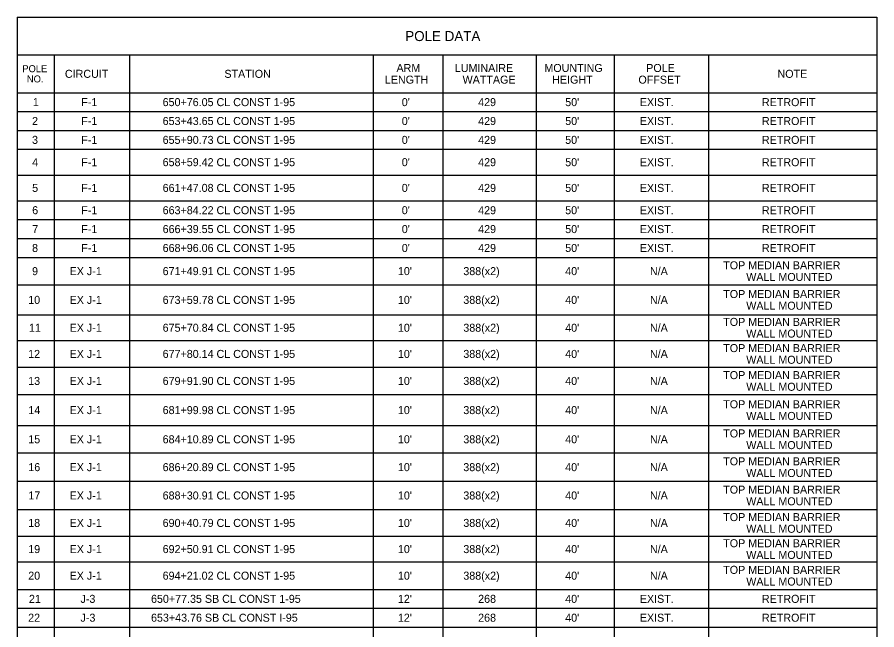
# Model space of a CAD drawing. Extents: x -838.2 to -802.1, y -2200.5 to -2187.7.
# Drawn here: x -838.21 to -830.69, y -2195.1 to -2189.75 of the extents above; entities that cross this region are included whole.
import ezdxf

# ---------------------------------------------------------------- set-up
doc = ezdxf.new("R2010")
doc.units = 0
for name, color, linetype in [('SumBoxBorder_dp', 7, 'Continuous'), ('SumBoxLines_dp', 7, 'Continuous'), ('SumBoxLinesMin_dp', 7, 'Continuous'), ('TextLabel', 7, 'Continuous')]:
    doc.layers.add(name, color=color, linetype=linetype)

msp = doc.modelspace()

# ---------------------------------------------------------------- linework, layer by layer
at = {"layer": 'SumBoxBorder_dp'}
for p, q in [((-838.2083, -2189.7484), (-830.6933, -2189.7484)), ((-838.2083, -2189.7484), (-838.2083, -2199.1009)), ((-830.6933, -2189.7484), (-830.6933, -2199.1009)), ((-830.6933, -2189.7484), (-830.6933, -2199.1009)), ((-838.2083, -2190.0784), (-830.6933, -2190.0784)), ((-838.2083, -2190.0784), (-830.6933, -2190.0784))]:
    msp.add_line(p, q, dxfattribs=at)
at = {"layer": 'SumBoxLines_dp'}
for p, q in [((-837.8858, -2190.0784), (-837.8858, -2199.1009)), ((-837.8858, -2190.0784), (-837.8858, -2199.1009)), ((-837.2258, -2190.0784), (-837.2258, -2199.1009)), ((-837.2258, -2190.0784), (-837.2258, -2199.1009)), ((-835.0958, -2190.0784), (-835.0958, -2197.0609)), ((-835.0958, -2190.0784), (-835.0958, -2199.1009)), ((-834.4883, -2190.0784), (-834.4883, -2199.1009)), ((-834.4883, -2190.0784), (-834.4883, -2199.1009)), ((-833.6708, -2190.0784), (-833.6708, -2199.1009)), ((-833.6708, -2190.0784), (-833.6708, -2199.1009)), ((-832.9883, -2190.0784), (-832.9883, -2199.1009)), ((-832.9883, -2190.0784), (-832.9883, -2199.1009)), ((-832.1633, -2190.0784), (-832.1633, -2199.1009)), ((-832.1633, -2190.0784), (-832.1633, -2199.1009)), ((-838.2083, -2190.4084), (-830.6933, -2190.4084))]:
    msp.add_line(p, q, dxfattribs=at)
at = {"layer": 'SumBoxLinesMin_dp'}
for p, q in [((-838.2083, -2190.4084), (-830.6933, -2190.4084)), ((-838.2083, -2190.5734), (-830.6933, -2190.5734)), ((-838.2083, -2190.5734), (-830.6933, -2190.5734)), ((-838.2083, -2190.7384), (-830.6933, -2190.7384)), ((-838.2083, -2190.7384), (-830.6933, -2190.7384)), ((-838.2083, -2190.9034), (-830.6933, -2190.9034)), ((-838.2083, -2190.9034), (-830.6933, -2190.9034)), ((-838.2083, -2191.1284), (-830.6933, -2191.1284)), ((-838.2083, -2191.1284), (-830.6933, -2191.1284)), ((-838.2083, -2191.3534), (-830.6933, -2191.3534)), ((-838.2083, -2191.3534), (-830.6933, -2191.3534)), ((-838.2083, -2191.5184), (-830.6933, -2191.5184)), ((-838.2083, -2191.5184), (-830.6933, -2191.5184)), ((-838.2083, -2191.6834), (-830.6933, -2191.6834)), ((-838.2083, -2191.6834), (-830.6933, -2191.6834)), ((-838.2083, -2191.8484), (-830.6933, -2191.8484)), ((-838.2083, -2191.8484), (-830.6933, -2191.8484)), ((-838.2083, -2192.0884), (-830.6933, -2192.0884)), ((-838.2083, -2192.0884), (-830.6933, -2192.0884)), ((-838.2083, -2192.3509), (-830.6933, -2192.3509)), ((-838.2083, -2192.3509), (-830.6933, -2192.3509)), ((-838.2083, -2192.5759), (-830.6933, -2192.5759)), ((-838.2083, -2192.5759), (-830.6933, -2192.5759)), ((-838.2083, -2192.8084), (-830.6933, -2192.8084)), ((-838.2083, -2192.8084), (-830.6933, -2192.8084)), ((-838.2083, -2193.0484), (-830.6933, -2193.0484)), ((-838.2083, -2193.0484), (-830.6933, -2193.0484)), ((-838.2083, -2193.3184), (-830.6933, -2193.3184)), ((-838.2083, -2193.3184), (-830.6933, -2193.3184)), ((-838.2083, -2193.5584), (-830.6933, -2193.5584)), ((-838.2083, -2193.5584), (-830.6933, -2193.5584)), ((-838.2083, -2193.8059), (-830.6933, -2193.8059)), ((-838.2083, -2193.8059), (-830.6933, -2193.8059)), ((-838.2083, -2194.0534), (-830.6933, -2194.0534)), ((-838.2083, -2194.0534), (-830.6933, -2194.0534)), ((-838.2083, -2194.2859), (-830.6933, -2194.2859)), ((-838.2083, -2194.2859), (-830.6933, -2194.2859)), ((-838.2083, -2194.5109), (-830.6933, -2194.5109)), ((-838.2083, -2194.5109), (-830.6933, -2194.5109)), ((-838.2083, -2194.7509), (-830.6933, -2194.7509)), ((-838.2083, -2194.7509), (-830.6933, -2194.7509)), ((-838.2083, -2194.9159), (-830.6933, -2194.9159)), ((-838.2083, -2194.9159), (-830.6933, -2194.9159)), ((-838.2083, -2195.0809), (-830.6933, -2195.0809)), ((-838.2083, -2195.0809), (-830.6933, -2195.0809))]:
    msp.add_line(p, q, dxfattribs=at)

# ---------------------------------------------------------------- texts
at = {"layer": 'TextLabel'}
for s, height, p in [('POLE DATA', 0.0875, (-834.8157, -2189.9572)), ('POLE', 0.06125, (-838.1637, -2190.2294)), ('ARM', 0.07, (-834.8926, -2190.2274)), ('LUMINAIRE', 0.07, (-834.3823, -2190.2274)), ('MOUNTING', 0.07, (-833.5993, -2190.2274)), ('POLE', 0.07, (-832.7091, -2190.2274)), ('CIRCUIT', 0.07, (-837.7912, -2190.2784)), ('STATION', 0.07, (-836.3967, -2190.2784)), ('NOTE', 0.07, (-831.5616, -2190.2784)), ('NO.', 0.06125, (-838.1238, -2190.3187)), ('LENGTH', 0.07, (-834.994, -2190.3294)), ('WATTAGE', 0.07, (-834.3145, -2190.3294)), ('HEIGHT', 0.07, (-833.5311, -2190.3294)), ('OFFSET', 0.07, (-832.7773, -2190.3294)), ('1', 0.07, (-838.0718, -2190.5259)), ('F-1', 0.07, (-837.6483, -2190.5259)), ('650+76.05 CL CONST 1-95', 0.07, (-836.9367, -2190.5259)), ("0'", 0.07, (-834.8462, -2190.5259)), ('429', 0.07, (-834.1784, -2190.5259)), ("50'", 0.07, (-833.4175, -2190.5259)), ('EXIST.', 0.07, (-832.7651, -2190.5259)), ('RETROFIT', 0.07, (-831.6976, -2190.5259)), ('2', 0.07, (-838.0785, -2190.6909)), ('F-1', 0.07, (-837.6483, -2190.6909)), ('653+43.65 CL CONST 1-95', 0.07, (-836.9367, -2190.6909)), ("0'", 0.07, (-834.8462, -2190.6909)), ('429', 0.07, (-834.1784, -2190.6909)), ("50'", 0.07, (-833.4175, -2190.6909)), ('EXIST.', 0.07, (-832.7651, -2190.6909)), ('RETROFIT', 0.07, (-831.6976, -2190.6909)), ('3', 0.07, (-838.0785, -2190.8559)), ('F-1', 0.07, (-837.6483, -2190.8559)), ('655+90.73 CL CONST 1-95', 0.07, (-836.9367, -2190.8559)), ("0'", 0.07, (-834.8462, -2190.8559)), ('429', 0.07, (-834.1784, -2190.8559)), ("50'", 0.07, (-833.4175, -2190.8559)), ('EXIST.', 0.07, (-832.7651, -2190.8559)), ('RETROFIT', 0.07, (-831.6976, -2190.8559)), ('4', 0.07, (-838.0771, -2191.0509)), ('F-1', 0.07, (-837.6483, -2191.0509)), ('658+59.42 CL CONST 1-95', 0.07, (-836.9367, -2191.0509)), ("0'", 0.07, (-834.8462, -2191.0509)), ('429', 0.07, (-834.1784, -2191.0509)), ("50'", 0.07, (-833.4175, -2191.0509)), ('EXIST.', 0.07, (-832.7651, -2191.0509)), ('RETROFIT', 0.07, (-831.6976, -2191.0509)), ('5', 0.07, (-838.0776, -2191.2759)), ('F-1', 0.07, (-837.6483, -2191.2759)), ('661+47.08 CL CONST 1-95', 0.07, (-836.9367, -2191.2759)), ("0'", 0.07, (-834.8462, -2191.2759)), ('429', 0.07, (-834.1784, -2191.2759)), ("50'", 0.07, (-833.4175, -2191.2759)), ('EXIST.', 0.07, (-832.7651, -2191.2759)), ('RETROFIT', 0.07, (-831.6976, -2191.2759)), ('6', 0.07, (-838.0771, -2191.4709)), ('F-1', 0.07, (-837.6483, -2191.4709)), ('663+84.22 CL CONST 1-95', 0.07, (-836.9367, -2191.4709)), ("0'", 0.07, (-834.8462, -2191.4709)), ('429', 0.07, (-834.1784, -2191.4709)), ("50'", 0.07, (-833.4175, -2191.4709)), ('EXIST.', 0.07, (-832.7651, -2191.4709)), ('RETROFIT', 0.07, (-831.6976, -2191.4709)), ('7', 0.07, (-838.0765, -2191.6359)), ('F-1', 0.07, (-837.6483, -2191.6359)), ('666+39.55 CL CONST 1-95', 0.07, (-836.9367, -2191.6359)), ("0'", 0.07, (-834.8462, -2191.6359)), ('429', 0.07, (-834.1784, -2191.6359)), ("50'", 0.07, (-833.4175, -2191.6359)), ('EXIST.', 0.07, (-832.7651, -2191.6359)), ('RETROFIT', 0.07, (-831.6976, -2191.6359)), ('8', 0.07, (-838.0783, -2191.8009)), ('F-1', 0.07, (-837.6483, -2191.8009)), ('668+96.06 CL CONST 1-95', 0.07, (-836.9367, -2191.8009)), ("0'", 0.07, (-834.8462, -2191.8009)), ('429', 0.07, (-834.1784, -2191.8009)), ("50'", 0.07, (-833.4175, -2191.8009)), ('EXIST.', 0.07, (-832.7651, -2191.8009)), ('RETROFIT', 0.07, (-831.6976, -2191.8009)), ('TOP MEDIAN BARRIER', 0.07, (-832.036, -2191.9524)), ('9', 0.07, (-838.0781, -2192.0034)), ('EX J-1', 0.07, (-837.7499, -2192.0034)), ('671+49.91 CL CONST 1-95', 0.07, (-836.9367, -2192.0034)), ("10'", 0.07, (-834.88, -2192.0034)), ('388(x2)', 0.07, (-834.3081, -2192.0034)), ("40'", 0.07, (-833.4175, -2192.0034)), ('N/A', 0.07, (-832.6765, -2192.0034)), ('WALL MOUNTED', 0.07, (-831.8346, -2192.0544)), ('10', 0.07, (-838.1118, -2192.2547)), ('EX J-1', 0.07, (-837.7499, -2192.2547)), ('673+59.78 CL CONST 1-95', 0.07, (-836.9367, -2192.2547)), ("10'", 0.07, (-834.88, -2192.2547)), ('388(x2)', 0.07, (-834.3081, -2192.2547)), ("40'", 0.07, (-833.4175, -2192.2547)), ('N/A', 0.07, (-832.6765, -2192.2547)), ('TOP MEDIAN BARRIER', 0.07, (-832.036, -2192.2037)), ('WALL MOUNTED', 0.07, (-831.8346, -2192.3057)), ('388(x2)', 0.07, (-834.3081, -2192.4984)), ('N/A', 0.07, (-832.6765, -2192.4984)), ('TOP MEDIAN BARRIER', 0.07, (-832.036, -2192.4474)), ('11', 0.07, (-838.1056, -2192.4984)), ('EX J-1', 0.07, (-837.7499, -2192.4984)), ('675+70.84 CL CONST 1-95', 0.07, (-836.9367, -2192.4984)), ("10'", 0.07, (-834.88, -2192.4984)), ("40'", 0.07, (-833.4175, -2192.4984)), ('WALL MOUNTED', 0.07, (-831.8346, -2192.5494)), ('TOP MEDIAN BARRIER', 0.07, (-832.036, -2192.6762)), ('12', 0.07, (-838.1124, -2192.7272)), ('EX J-1', 0.07, (-837.7499, -2192.7272)), ('677+80.14 CL CONST 1-95', 0.07, (-836.9367, -2192.7272)), ("10'", 0.07, (-834.88, -2192.7272)), ('388(x2)', 0.07, (-834.3081, -2192.7272)), ("40'", 0.07, (-833.4175, -2192.7272)), ('N/A', 0.07, (-832.6765, -2192.7272)), ('WALL MOUNTED', 0.07, (-831.8346, -2192.7782)), ('TOP MEDIAN BARRIER', 0.07, (-832.036, -2192.9124)), ('13', 0.07, (-838.1124, -2192.9634)), ('EX J-1', 0.07, (-837.7499, -2192.9634)), ('679+91.90 CL CONST 1-95', 0.07, (-836.9367, -2192.9634)), ("10'", 0.07, (-834.88, -2192.9634)), ('388(x2)', 0.07, (-834.3081, -2192.9634)), ("40'", 0.07, (-833.4175, -2192.9634)), ('N/A', 0.07, (-832.6765, -2192.9634)), ('WALL MOUNTED', 0.07, (-831.8346, -2193.0144)), ('TOP MEDIAN BARRIER', 0.07, (-832.036, -2193.1674)), ('14', 0.07, (-838.111, -2193.2184)), ('EX J-1', 0.07, (-837.7499, -2193.2184)), ('681+99.98 CL CONST 1-95', 0.07, (-836.9367, -2193.2184)), ("10'", 0.07, (-834.88, -2193.2184)), ('388(x2)', 0.07, (-834.3081, -2193.2184)), ("40'", 0.07, (-833.4175, -2193.2184)), ('N/A', 0.07, (-832.6765, -2193.2184)), ('WALL MOUNTED', 0.07, (-831.8346, -2193.2694)), ('684+10.89 CL CONST 1-95', 0.07, (-836.9367, -2193.4734)), ("10'", 0.07, (-834.88, -2193.4734)), ('388(x2)', 0.07, (-834.3081, -2193.4734)), ("40'", 0.07, (-833.4175, -2193.4734)), ('N/A', 0.07, (-832.6765, -2193.4734)), ('TOP MEDIAN BARRIER', 0.07, (-832.036, -2193.4224)), ('15', 0.07, (-838.1115, -2193.4734)), ('EX J-1', 0.07, (-837.7499, -2193.4734)), ('WALL MOUNTED', 0.07, (-831.8346, -2193.5244)), ('TOP MEDIAN BARRIER', 0.07, (-832.036, -2193.6662)), ('16', 0.07, (-838.111, -2193.7172)), ('EX J-1', 0.07, (-837.7499, -2193.7172)), ('686+20.89 CL CONST 1-95', 0.07, (-836.9367, -2193.7172)), ("10'", 0.07, (-834.88, -2193.7172)), ('388(x2)', 0.07, (-834.3081, -2193.7172)), ("40'", 0.07, (-833.4175, -2193.7172)), ('N/A', 0.07, (-832.6765, -2193.7172)), ('WALL MOUNTED', 0.07, (-831.8346, -2193.7682)), ('TOP MEDIAN BARRIER', 0.07, (-832.036, -2193.9137)), ('17', 0.07, (-838.1104, -2193.9647)), ('EX J-1', 0.07, (-837.7499, -2193.9647)), ('688+30.91 CL CONST 1-95', 0.07, (-836.9367, -2193.9647)), ("10'", 0.07, (-834.88, -2193.9647)), ('388(x2)', 0.07, (-834.3081, -2193.9647)), ("40'", 0.07, (-833.4175, -2193.9647)), ('N/A', 0.07, (-832.6765, -2193.9647)), ('WALL MOUNTED', 0.07, (-831.8346, -2194.0157)), ('18', 0.07, (-838.1121, -2194.2047)), ('EX J-1', 0.07, (-837.7499, -2194.2047)), ('690+40.79 CL CONST 1-95', 0.07, (-836.9367, -2194.2047)), ("10'", 0.07, (-834.88, -2194.2047)), ('388(x2)', 0.07, (-834.3081, -2194.2047)), ("40'", 0.07, (-833.4175, -2194.2047)), ('N/A', 0.07, (-832.6765, -2194.2047)), ('TOP MEDIAN BARRIER', 0.07, (-832.036, -2194.1537)), ('WALL MOUNTED', 0.07, (-831.8346, -2194.2557)), ('19', 0.07, (-838.112, -2194.4334)), ('EX J-1', 0.07, (-837.7499, -2194.4334)), ('692+50.91 CL CONST 1-95', 0.07, (-836.9367, -2194.4334)), ("10'", 0.07, (-834.88, -2194.4334)), ('388(x2)', 0.07, (-834.3081, -2194.4334)), ("40'", 0.07, (-833.4175, -2194.4334)), ('N/A', 0.07, (-832.6765, -2194.4334)), ('TOP MEDIAN BARRIER', 0.07, (-832.036, -2194.3824)), ('WALL MOUNTED', 0.07, (-831.8346, -2194.4844)), ('20', 0.07, (-838.1118, -2194.6659)), ('EX J-1', 0.07, (-837.7499, -2194.6659)), ('694+21.02 CL CONST 1-95', 0.07, (-836.9367, -2194.6659)), ("10'", 0.07, (-834.88, -2194.6659)), ('388(x2)', 0.07, (-834.3081, -2194.6659)), ("40'", 0.07, (-833.4175, -2194.6659)), ('N/A', 0.07, (-832.6765, -2194.6659)), ('TOP MEDIAN BARRIER', 0.07, (-832.036, -2194.6149)), ('WALL MOUNTED', 0.07, (-831.8346, -2194.7169)), ('21', 0.07, (-838.1056, -2194.8684)), ('J-3', 0.07, (-837.655, -2194.8684)), ('650+77.35 SB CL CONST 1-95', 0.07, (-837.0383, -2194.8684)), ("12'", 0.07, (-834.88, -2194.8684)), ('268', 0.07, (-834.1785, -2194.8684)), ("40'", 0.07, (-833.4175, -2194.8684)), ('EXIST.', 0.07, (-832.7651, -2194.8684)), ('RETROFIT', 0.07, (-831.6976, -2194.8684)), ('22', 0.07, (-838.1124, -2195.0334)), ('J-3', 0.07, (-837.655, -2195.0334)), ('653+43.76 SB CL CONST I-95', 0.07, (-837.0383, -2195.0334)), ("12'", 0.07, (-834.88, -2195.0334)), ('268', 0.07, (-834.1785, -2195.0334)), ("40'", 0.07, (-833.4175, -2195.0334)), ('EXIST.', 0.07, (-832.7651, -2195.0334)), ('RETROFIT', 0.07, (-831.6976, -2195.0334))]:
    msp.add_text(s, height=height, dxfattribs=at).set_placement(p)

doc.saveas('drawing.dxf')
